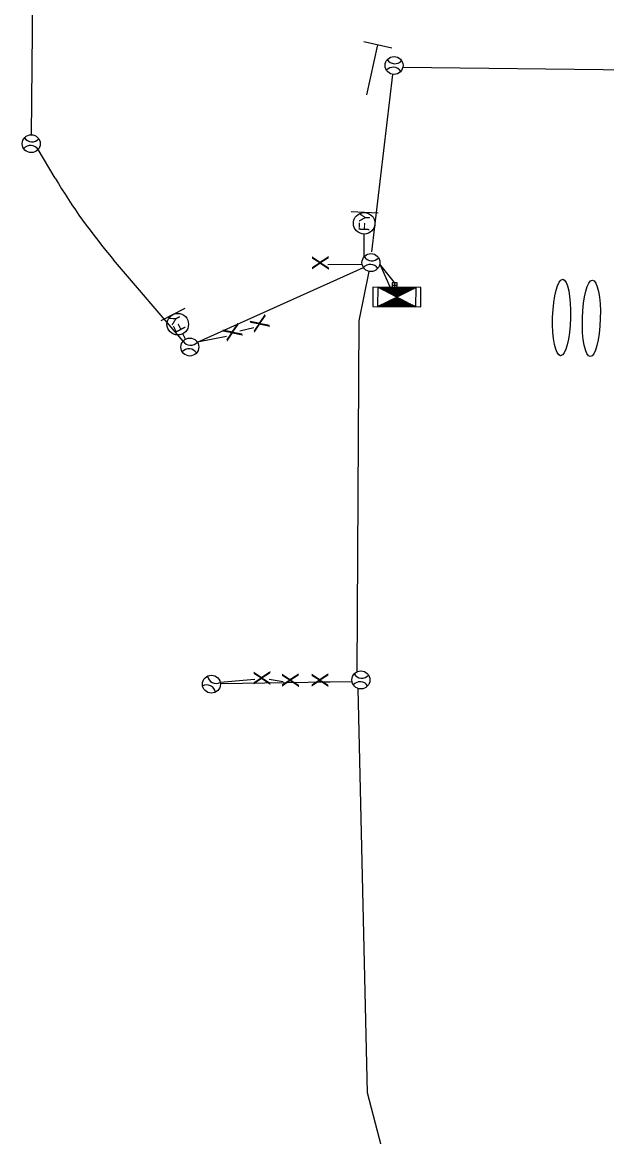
# Model space of a CAD drawing. Extents: x 601562 to 605316, y 332050 to 402250.
# Drawn here: x 602540.9 to 602785.1, y 365625.4 to 366091.2 of the extents above; entities that cross this region are included whole.
import ezdxf

# ---------------------------------------------------------------- set-up
doc = ezdxf.new("R2010")
doc.units = 0
doc.layers.add('P_FTMS', color=7, linetype='Continuous')
doc.layers.add('P_FTMSConduit', color=7, linetype='Continuous')

# ---------------------------------------------------------------- blocks, each defined once
blk = doc.blocks.new('FTMS_FERA')
at = {"layer": 'P_FTMS'}
for p, q in [((-65.1, 36.6), (-65.1, -36.6)), ((65.1, 0), (-65.1, 0))]:
    blk.add_line(p, q, dxfattribs=at)
blk = doc.blocks.new('FTMS_FCB')
at = {"layer": 'P_FTMS'}
for p, q in [((-48.3, 24.1), (-48, 24.4)), ((-45.5, 22.7), (-47.1, 24.4)), ((-46.9, 23.4), (-46, 24.4)), ((-45.5, 22.8), (-43.9, 24.4)), ((-41.4, 20.7), (-45.1, 24.4)), ((-44.1, 22.1), (-41.8, 24.4)), ((-37.2, 18.6), (-43, 24.4)), ((-42.8, 21.4), (-39.8, 24.4)), ((-41.4, 20.7), (-37.7, 24.4)), ((-33.1, 16.5), (-40.9, 24.4)), ((-40, 20), (-35.6, 24.4)), ((-29, 14.5), (-38.9, 24.4)), ((-38.6, 19.3), (-33.6, 24.4)), ((-37.2, 18.6), (-31.5, 24.4)), ((-24.8, 12.4), (-36.8, 24.4)), ((-35.9, 17.9), (-29.4, 24.4)), ((-20.7, 10.3), (-34.7, 24.4)), ((-34.5, 17.2), (-27.3, 24.4)), ((-33.1, 16.5), (-25.3, 24.4)), ((-16.5, 8.3), (-32.7, 24.4)), ((-31.7, 15.9), (-23.2, 24.4)), ((-12.4, 6.2), (-30.6, 24.4)), ((-30.3, 15.2), (-21.1, 24.4)), ((-29, 14.5), (-19.1, 24.4)), ((-8.3, 4.1), (-28.5, 24.4)), ((-27.6, 13.8), (-17, 24.4)), ((-4.1, 2.1), (-26.4, 24.4)), ((-26.2, 13.1), (-14.9, 24.4)), ((-24.8, 12.4), (-12.9, 24.4)), ((0, 0), (-24.4, 24.4)), ((-24.4, -24.4), (0, 0)), ((-23.5, 11.7), (-10.8, 24.4)), ((1.4, 0.7), (-22.3, 24.4)), ((-22.1, 11), (-8.7, 24.4)), ((-20.7, 10.3), (-6.7, 24.4)), ((2.8, 1.4), (-20.2, 24.4)), ((-19.3, 9.7), (-4.6, 24.4)), ((4.1, 2.1), (-18.2, 24.4)), ((-17.9, 9), (-2.5, 24.4)), ((-16.6, 8.3), (-0.4, 24.4)), ((5.5, 2.8), (-16.1, 24.4)), ((-15.2, 7.6), (1.6, 24.4)), ((6.9, 3.4), (-14, 24.4)), ((-13.8, 6.9), (3.7, 24.4)), ((-12.4, 6.2), (5.8, 24.4)), ((8.3, 4.1), (-12, 24.4)), ((-11, 5.5), (7.8, 24.4)), ((9.7, 4.8), (-9.9, 24.4)), ((-9.7, 4.8), (9.9, 24.4)), ((-8.3, 4.1), (12, 24.4)), ((11, 5.5), (-7.8, 24.4)), ((-6.9, 3.4), (14, 24.4)), ((12.4, 6.2), (-5.8, 24.4)), ((-5.5, 2.8), (16.1, 24.4)), ((-4.1, 2.1), (18.2, 24.4)), ((13.8, 6.9), (-3.7, 24.4)), ((-2.8, 1.4), (20.2, 24.4)), ((15.2, 7.6), (-1.6, 24.4)), ((-1.4, 0.7), (22.3, 24.4)), ((0, 0), (24.4, 24.4)), ((24.4, -24.4), (0, 0)), ((16.6, 8.3), (0.4, 24.4)), ((17.9, 9), (2.5, 24.4)), ((4.1, 2.1), (26.5, 24.4)), ((19.3, 9.7), (4.6, 24.4)), ((20.7, 10.3), (6.7, 24.4)), ((8.3, 4.1), (28.5, 24.4)), ((22.1, 11), (8.7, 24.4)), ((23.4, 11.7), (10.8, 24.4)), ((12.4, 6.2), (30.6, 24.4)), ((24.8, 12.4), (12.9, 24.4)), ((26.2, 13.1), (14.9, 24.4)), ((16.6, 8.3), (32.7, 24.4)), ((27.6, 13.8), (17, 24.4)), ((29, 14.5), (19.1, 24.4)), ((20.7, 10.3), (34.7, 24.4)), ((30.3, 15.2), (21.1, 24.4)), ((31.7, 15.9), (23.2, 24.4)), ((24.8, 12.4), (36.8, 24.4)), ((33.1, 16.6), (25.3, 24.4)), ((34.5, 17.2), (27.3, 24.4)), ((29, 14.5), (38.9, 24.4)), ((35.9, 17.9), (29.4, 24.4)), ((37.2, 18.6), (31.5, 24.4)), ((33.1, 16.6), (40.9, 24.4)), ((38.6, 19.3), (33.5, 24.4)), ((40, 20), (35.6, 24.4)), ((37.2, 18.6), (43, 24.4)), ((41.4, 20.7), (37.7, 24.4)), ((42.8, 21.4), (39.8, 24.4)), ((41.4, 20.7), (45.1, 24.4)), ((44.1, 22.1), (41.8, 24.4)), ((45.5, 22.8), (43.9, 24.4)), ((45.5, 22.8), (47.1, 24.4)), ((46.9, 23.5), (46, 24.4)), ((48.3, 24.1), (48, 24.4)), ((-48, -24.4), (-48.3, -24.1)), ((-47.2, -24.4), (-45.5, -22.8)), ((-45.9, -24.4), (-46.9, -23.5)), ((-43.9, -24.4), (-45.5, -22.8)), ((-45.1, -24.4), (-41.4, -20.7)), ((-41.8, -24.4), (-44.1, -22.1)), ((-43, -24.4), (-37.3, -18.6)), ((-39.7, -24.4), (-42.8, -21.4)), ((-37.7, -24.4), (-41.4, -20.7)), ((-41, -24.4), (-33.1, -16.6)), ((-35.6, -24.4), (-40, -20)), ((-38.9, -24.4), (-29, -14.5)), ((-33.5, -24.4), (-38.6, -19.3)), ((-31.5, -24.4), (-37.2, -18.6)), ((-36.8, -24.4), (-24.8, -12.4)), ((-29.4, -24.4), (-35.9, -17.9)), ((-34.8, -24.4), (-20.7, -10.4)), ((-27.3, -24.4), (-34.5, -17.2)), ((-25.3, -24.4), (-33.1, -16.6)), ((-32.7, -24.4), (-16.6, -8.3)), ((-23.2, -24.4), (-31.7, -15.9)), ((-30.6, -24.4), (-12.4, -6.2)), ((-21.1, -24.4), (-30.3, -15.2)), ((-19, -24.4), (-29, -14.5)), ((-28.5, -24.4), (-8.3, -4.1)), ((-17, -24.4), (-27.6, -13.8)), ((-26.5, -24.4), (-4.1, -2.1)), ((-14.9, -24.4), (-26.2, -13.1)), ((-12.8, -24.4), (-24.8, -12.4)), ((-10.8, -24.4), (-23.4, -11.7)), ((-22.3, -24.4), (1.4, -0.7)), ((-8.7, -24.4), (-22.1, -11)), ((-6.6, -24.4), (-20.7, -10.3)), ((-20.3, -24.4), (2.8, -1.4)), ((-4.6, -24.4), (-19.3, -9.7)), ((-18.2, -24.4), (4.1, -2.1)), ((-2.5, -24.4), (-17.9, -9)), ((-0.4, -24.4), (-16.6, -8.3)), ((-16.1, -24.4), (5.5, -2.8)), ((1.6, -24.4), (-15.2, -7.6)), ((-14.1, -24.4), (6.9, -3.4)), ((3.7, -24.4), (-13.8, -6.9)), ((5.8, -24.4), (-12.4, -6.2)), ((-12, -24.4), (8.3, -4.1)), ((7.8, -24.4), (-11, -5.5)), ((-9.9, -24.4), (9.7, -4.8)), ((9.9, -24.4), (-9.7, -4.8)), ((12, -24.4), (-8.3, -4.1)), ((-7.8, -24.4), (11, -5.5)), ((14.1, -24.4), (-6.9, -3.5)), ((-5.8, -24.4), (12.4, -6.2)), ((16.1, -24.4), (-5.5, -2.8)), ((18.2, -24.4), (-4.1, -2.1)), ((-3.7, -24.4), (13.8, -6.9)), ((20.3, -24.4), (-2.8, -1.4)), ((-1.6, -24.4), (15.2, -7.6)), ((22.3, -24.4), (-1.4, -0.7)), ((0.4, -24.4), (16.6, -8.3)), ((2.5, -24.4), (17.9, -9)), ((26.5, -24.4), (4.1, -2.1)), ((4.6, -24.4), (19.3, -9.7)), ((6.6, -24.4), (20.7, -10.3)), ((28.5, -24.4), (8.3, -4.1)), ((8.7, -24.4), (22.1, -11)), ((10.8, -24.4), (23.4, -11.7)), ((30.6, -24.4), (12.4, -6.2)), ((12.8, -24.4), (24.8, -12.4)), ((14.9, -24.4), (26.2, -13.1)), ((32.7, -24.4), (16.6, -8.3)), ((17, -24.4), (27.6, -13.8)), ((19.1, -24.4), (29, -14.5)), ((34.7, -24.4), (20.7, -10.3)), ((21.1, -24.4), (30.3, -15.2)), ((23.2, -24.4), (31.7, -15.9)), ((36.8, -24.4), (24.8, -12.4)), ((25.3, -24.4), (33.1, -16.6)), ((27.3, -24.4), (34.5, -17.2)), ((38.9, -24.4), (29, -14.5)), ((29.4, -24.4), (35.9, -17.9)), ((31.5, -24.4), (37.2, -18.6)), ((40.9, -24.4), (33.1, -16.6)), ((33.5, -24.4), (38.6, -19.3)), ((35.6, -24.4), (40, -20)), ((43, -24.4), (37.2, -18.6)), ((37.7, -24.4), (41.4, -20.7)), ((39.7, -24.4), (42.8, -21.4)), ((45.1, -24.4), (41.4, -20.7)), ((41.8, -24.4), (44.1, -22.1)), ((43.9, -24.4), (45.5, -22.8)), ((47.2, -24.4), (45.5, -22.8)), ((46, -24.4), (46.9, -23.5)), ((48, -24.4), (48.3, -24.1))]:
    blk.add_line(p, q, dxfattribs=at)
for points in [[(61, 24.4), (-61, 24.4), (-61, -24.4), (61, -24.4)], [(48.8, 24.4), (-48.8, 24.4), (-48.8, -24.4), (48.8, -24.4)], [(48.8, 24.4), (0, 0), (-48.8, 24.4)], [(48.8, -24.4), (-48.8, -24.4), (0, 0)]]:
    blk.add_lwpolyline(points, close=True, dxfattribs=at)
blk = doc.blocks.new('FTMS')
at = {"layer": 'P_FTMS'}
for p, q in [((-23, 0), (26, 0)), ((0, 24), (0, -24))]:
    blk.add_line(p, q, dxfattribs=at)
blk.add_lwpolyline([(26, -24), (26, 24), (-23, 24), (-23, -24)], close=True, dxfattribs=at)
blk = doc.blocks.new('FTMS_FFY')
at = {"layer": 'P_FTMS'}
blk.add_line((36.6, -45.7), (36.6, 45.7), dxfattribs=at)
blk.add_circle((0, 0), 36.6, dxfattribs=at)
blk.add_text('FY', height=36.58, dxfattribs=at).set_placement((-26.8, -18.3))

msp = doc.modelspace()

# ---------------------------------------------------------------- linework, layer by layer
at = {"layer": 'P_FTMS'}
for centre in [(602696.22, 366073.13), (602544.63, 366040.44), (602686.57, 365990.75), (602610.89, 365955.44), (602682.37, 365816.32), (602619.91, 365814.52)]:
    msp.add_circle(centre, 3.75, dxfattribs=at)
for centre, start, end in [((602696.55, 366077.62), 212.6299, 318.8855), ((602695.88, 366068.65), 32.6299, 138.8855), ((602544.97, 366044.93), 212.6299, 318.8855), ((602544.3, 366035.95), 32.6299, 138.8855), ((602686.9, 365995.24), 212.6299, 318.8855), ((602686.24, 365986.26), 32.6299, 138.8855), ((602610.56, 365950.95), 32.6299, 138.8855), ((602611.22, 365959.93), 212.6299, 318.8855), ((602682.7, 365820.81), 212.6299, 318.8855), ((602617.92, 365810.49), 10.5652, 116.8209), ((602621.91, 365818.55), 190.5652, 296.8209), ((602682.03, 365811.83), 32.6299, 138.8855)]:
    msp.add_arc(centre, 3.75, start, end, dxfattribs=at)
for centre in [(602766.24, 365967.79), (602778.67, 365967.43)]:
    msp.add_ellipse(centre, major_axis=(0.46, 15.97), ratio=0.23471, dxfattribs=at)
at = {"layer": 'P_FTMSConduit'}
for p, q in [((602544.68, 366044.19), (602546.57, 366207.33)), ((602699.9, 366072.41), (602900.93, 366070.13)), ((602686.9, 365995.24), (602695.77, 366069.41)), ((602554.59, 366026.03), (602547.46, 366037.97)), ((602683.74, 365993.22), (602683.75, 366002.67)), ((602608.07, 365957.9), (602579.04, 365991.94)), ((602614.05, 365957.46), (602683.41, 365988.73)), ((602668.49, 365989.99), (602682.89, 365990.03)), ((602668.49, 365989.99), (602682.89, 365990.03)), ((602681.58, 365966.35), (602685.82, 365987.08)), ((602696.42, 365982.36), (602690.27, 365990.12)), ((602690.27, 365990.12), (602694.63, 365980.37)), ((602637.61, 365963.52), (602631.78, 365962.12)), ((602680.79, 365819.72), (602681.58, 365966.35)), ((602609.14, 365958.75), (602607.95, 365961.01)), ((602626.22, 365959.85), (602614.05, 365957.46)), ((602638.03, 365816.44), (602623.57, 365815.19)), ((602623.65, 365814.78), (602678.69, 365815.6)), ((602649.96, 365815.56), (602644.03, 365816.45)), ((602664.29, 365815.56), (602678.69, 365815.6)), ((602685.16, 365643.73), (602681.26, 365812.74)), ((602696.77, 365598.92), (602685.16, 365643.73))]:
    msp.add_line(p, q, dxfattribs=at)
msp.add_arc((602769.25, 366154.17), 250, 210.8343, 220.4612, dxfattribs=at)

# ---------------------------------------------------------------- block references
at = {"layer": 'P_FTMS'}
for name, p, xscale, yscale, rotation in [('FTMS_FERA', (602687.14, 366071.28), 0.16404166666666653, 0.16404166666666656, -102.34273939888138), ('FTMS_FFY', (602683.75, 366007.17), 0.12303125, 0.12303125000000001, 87.46211808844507), ('FTMS_FCB', (602697.39, 365976.35), 0.16404166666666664, 0.16404166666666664, 179.62225148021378), ('FTMS_FFY', (602605.84, 365964.99), 0.12303125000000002, 0.12303125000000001, 117.56653042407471)]:
    msp.add_blockref(name, p, dxfattribs=dict(at, xscale=xscale, yscale=yscale, rotation=rotation))
at = {"layer": 'P_FTMS', "xscale": 0.04101041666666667, "yscale": 0.04101041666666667}
msp.add_blockref('FTMS', (602696.42, 365981.36), dxfattribs=at)

# ---------------------------------------------------------------- texts
at = {"layer": 'P_FTMSConduit'}
for rotation, p in [(90.1543, (602668.98, 365987.53)), (90.1543, (602668.98, 365987.53)), (112.2583, (602644.54, 365963.69)), (112.2583, (602633.16, 365960.02)), (90.1937, (602644.52, 365813.99)), (90.1937, (602656.45, 365813.11)), (90.1543, (602668.82, 365813.11))]:
    msp.add_text('X', height=7, rotation=rotation, dxfattribs=at).set_placement(p)

doc.saveas('drawing.dxf')
